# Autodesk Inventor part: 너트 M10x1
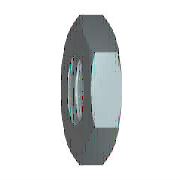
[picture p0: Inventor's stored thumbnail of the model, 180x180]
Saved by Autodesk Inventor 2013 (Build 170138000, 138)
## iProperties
Created: 2012-02
Part Number: 너트 M10x1
Material: 강철, 연강
Description: 6각 가는 너트 - 이중 모따기(부품 등급 A) - 정밀 나사산
Document SubType Name: Modeling
Standard: JIS B 1181
Designer: mduedu
Standards Organization: JIS
Language: ko-KR
Size Designation: M10x1
Categories: <MemberInstance><Categories><Category DisplayName="조임쇠" InternalName="e4da775c-781d-43d5-af7c-5136215cf5a6" Mnemonic="FSTN"><Category DisplayName="너트" InternalN
Density: 7.86 g/cm^3
IsCustomPart: 1
Author: mduedu
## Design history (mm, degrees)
node "MSC_A1"
node "MSC_PT1"
node "MSC_PT2"
node "MSC_PF1"
body "Solid1"
sketch "스케치1"
  geometry: L1 (8, 4.619)-(8, -4.619); L2 (8, -4.619)-(0, -9.238); L3 (0, -9.238)-(-8, -4.619); L4 (-8, -4.619)-(-8, 4.619); L5 (-8, 4.619)-(0, 9.238); L6 (0, 9.238)-(8, 4.619); C1 r 8 at (0, 0); 2 further points
  constraints: 12 end point, 2 coincident, 1 centre point, 1 tangent, 1 vertical, 11 other
  dimensions: "d0" = 16 diameter of C1 (= ParS)
extrude "돌출1" new body sketch "스케치1" distance "d1" = 5 (= M); taper "d2" = 0 deg
sketch "스케치2"
  geometry: L1 (-8, 4.619)-(0, 9.238) reference; L2 (0, -9.238)-(-8, -4.619) reference; L3 (-8, 4.619)-(8, -4.619); L4 (-8, -4.619)-(8, 4.619); 1 further point
  constraints: 4 end point, 2 midpoint, 2 parallel
hole "구멍1" sketch "스케치2" diameter "d3" = 8.91747; stored, may be unused: countersink angle "d7" = 90 deg, drill point angle "d9" = 118 deg; dims "d4" = 6, "d5" = 4, "d6" = 2, "d8" = 8
chamfer "모따기1" distance "d10" = 0.5 (= 0.5 x PTC); stored, may be unused: second distance "d11" = 2, angle "d12" = 45 deg
revolve "회전1" stored, may be unused: angle "d15" = 90 deg
sketch "스케치3"
  geometry: L1 (-9.238, 5)-(-9.238, 4.285); L2 (-9.238, 4.285)-(-8, 5); L3 (-8, 5)-(-9.238, 5); L4 (-9.238, 0.715)-(-9.238, 0); L5 (-9.238, 0)-(-8, 0); L6 (-8, 0)-(-9.238, 0.715); L7 (0, 6)-(0, -1) reference; L8 (-4.619, 5)-(-9.238, 5) reference; L9 (-4.619, 0)-(-9.238, 0) reference; L10 (-9.238, 0)-(-9.238, 5) reference
  constraints: 12 end point, 4 collinear, 3 perpendicular, 2 equal length, 1 vertical
  dimensions: "d13" = 30 deg angle of L2 L3; "d14" = 8 distance from line of L2.end L7 (= 0.5 x ParS)
other parameters: "ParS" = 16 [user parameter; used in 2 equation terms], "M" = 5 [user parameter; used in 1 equation term], "PTC" = 1 [user parameter; used in 1 equation term], "d17" = 0, "d18" = 0, "d19" = 0, "d20" = 0, "d21" = 0, "d22" = 0, "d23" = 0
